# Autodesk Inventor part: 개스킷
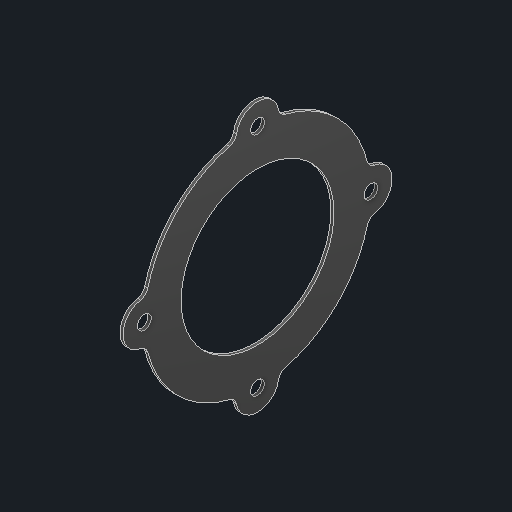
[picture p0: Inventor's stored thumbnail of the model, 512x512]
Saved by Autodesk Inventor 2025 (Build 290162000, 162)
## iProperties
Created: 2025-08
Part Number: 개스킷
Material: 황동, 연질 노란색
Document SubType Name: Modeling
Designer: infra17
Density: 8.47 g/cm^3
Appearance: 기본값
Author: jhkim
Sending System: Autodesk Inventor 2026
Preprocessor: ST-DEVELOPER v20.1
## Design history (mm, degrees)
feature "솔리드2"
node "솔리드1"
